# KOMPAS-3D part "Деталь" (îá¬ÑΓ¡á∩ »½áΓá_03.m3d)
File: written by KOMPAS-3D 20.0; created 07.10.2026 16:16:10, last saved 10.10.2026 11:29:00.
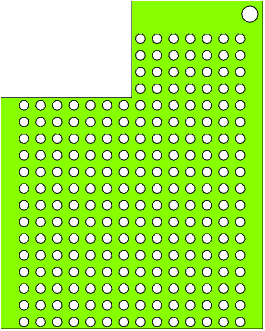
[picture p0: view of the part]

Document properties: Полное имя файла: D:\myProjects\Progect_esp32\box_compas\Макетная плата_4х6.m3d

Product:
- Part/product: Деталь
    Масса: 0.0153693

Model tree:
1. Эскиз:1
2. Элемент выдавливания:1
     Расстояние 1 = 1.5
3. Эскиз:2  (with: Элемент выдавливания:1)
4. Элемент выдавливания:2
     Расстояние 2 = 1.5
5. Эскиз:3  (with: Элемент выдавливания:1)
6. Элемент выдавливания:3
     Расстояние 2 = 1.5
7. Массив по сетке:1  (with: Элемент выдавливания:3, Эскиз:3, Элемент выдавливания:1)  (280 pattern instances)
     Шаг 1 = 2.54; Угол раствора = -90; Шаг 2 = 2.54
8. Массив по сетке:2  (with: Элемент выдавливания:2, Эскиз:2, Элемент выдавливания:1)  (4 pattern instances)
     Шаг 1 = 56; Угол раствора = 90; Шаг 2 = 36; Геометрический массив = 128
9. Эскиз:4  (with: Элемент выдавливания:1)
10. Элемент выдавливания:4
     Расстояние 2 = 1.5
11. Эскиз:5  (with: Элемент выдавливания:1)
12. Элемент выдавливания:5
     Расстояние 2 = 1.5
